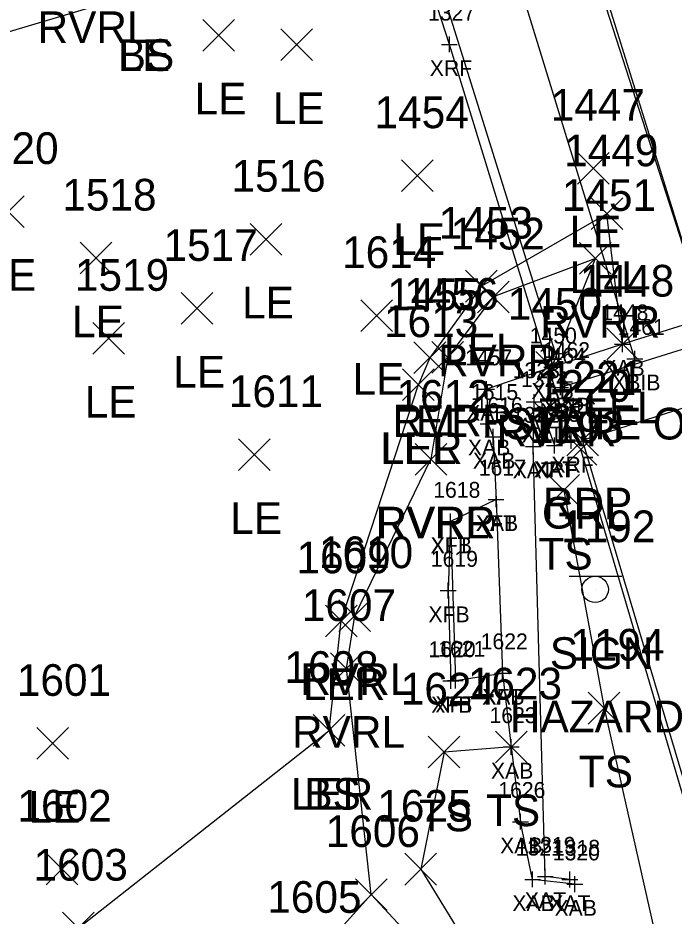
# Model space of a CAD drawing. Extents: x 1620157 to 1620595, y 115111 to 117885.
# Drawn here: x 1620300.9 to 1620342.3, y 115358.6 to 115415.3 of the extents above; entities that cross this region are included whole.
import ezdxf

# ---------------------------------------------------------------- set-up
doc = ezdxf.new("R2010")
doc.units = 0
for name, color, linetype in [('B_A', 7, 'Continuous'), ('B_I', 7, 'Continuous'), ('B_TIC', 7, 'Continuous'), ('BB', 7, 'Continuous'), ('BELB', 7, 'Continuous'), ('BFT', 7, 'Continuous'), ('BR', 7, 'Continuous'), ('BSE', 7, 'Continuous'), ('BSUBM', 7, 'Continuous'), ('C_C', 7, 'Continuous'), ('L_A', 7, 'Continuous'), ('L_I', 7, 'Continuous'), ('L_TIC', 7, 'Continuous'), ('LARO', 7, 'Continuous'), ('LAWE', 7, 'Continuous'), ('LELB', 7, 'Continuous'), ('P_A', 7, 'Continuous'), ('P_I', 7, 'Continuous'), ('P_TIC', 7, 'Continuous'), ('PET', 7, 'Continuous'), ('R_A', 7, 'Continuous'), ('R_I', 7, 'Continuous'), ('R_TIC', 7, 'Continuous'), ('RGR', 7, 'Continuous'), ('S_A', 7, 'Continuous'), ('S_C', 7, 'Continuous'), ('S_I', 7, 'Continuous'), ('SSGN', 7, 'Continuous')]:
    doc.layers.add(name, color=color, linetype=linetype)

msp = doc.modelspace()

# ---------------------------------------------------------------- linework, layer by layer
at = {"layer": 'B_TIC'}
for p, q in [((1620328.105, 115413.59), (1620328.18, 115413.59)), ((1620339.038, 115394.674), (1620339.113, 115394.674)), ((1620339.811, 115393.755), (1620339.886, 115393.755)), ((1620334.567, 115393.214), (1620334.642, 115393.214)), ((1620335.378, 115392.294), (1620335.453, 115392.294)), ((1620330.443, 115391.836), (1620330.519, 115391.836)), ((1620335.116, 115391.945), (1620335.192, 115391.945)), ((1620333.45, 115391.022), (1620333.525, 115391.022)), ((1620333.966, 115390.461), (1620334.041, 115390.461)), ((1620330.556, 115389.649), (1620330.631, 115389.649)), ((1620330.873, 115388.823), (1620330.949, 115388.823)), ((1620335.783, 115388.568), (1620335.858, 115388.568)), ((1620333.4, 115388.211), (1620333.476, 115388.211)), ((1620334.734, 115388.271), (1620334.809, 115388.271)), ((1620334.734, 115388.271), (1620334.809, 115388.271)), ((1620331.048, 115384.876), (1620331.124, 115384.876)), ((1620331.048, 115384.876), (1620331.124, 115384.876)), ((1620328.171, 115383.477), (1620328.247, 115383.477)), ((1620328.171, 115383.477), (1620328.247, 115383.477)), ((1620328.024, 115379.121), (1620328.099, 115379.121)), ((1620331.449, 115373.918), (1620331.525, 115373.918)), ((1620331.449, 115373.918), (1620331.525, 115373.918)), ((1620328.199, 115373.416), (1620328.275, 115373.416)), ((1620328.484, 115373.445), (1620328.559, 115373.445)), ((1620332.008, 115369.254), (1620332.083, 115369.254)), ((1620332.589, 115364.537), (1620332.664, 115364.537)), ((1620332.589, 115364.537), (1620332.664, 115364.537)), ((1620334.16, 115361.076), (1620334.236, 115361.076)), ((1620333.361, 115360.897), (1620333.436, 115360.897)), ((1620335.71, 115360.89), (1620335.785, 115360.89)), ((1620336.021, 115360.595), (1620336.097, 115360.595))]:
    msp.add_line(p, q, dxfattribs=at)
for points in [[(1620328.101, 115413.09), (1620328.101, 115414.09)], [(1620327.601, 115413.59), (1620328.601, 115413.59)], [(1620339.034, 115394.174), (1620339.034, 115395.174)], [(1620338.534, 115394.674), (1620339.534, 115394.674)], [(1620339.807, 115393.255), (1620339.807, 115394.255)], [(1620334.564, 115392.714), (1620334.564, 115393.714)], [(1620339.307, 115393.755), (1620340.307, 115393.755)], [(1620334.064, 115393.214), (1620335.064, 115393.214)], [(1620330.44, 115391.336), (1620330.44, 115392.336)], [(1620334.874, 115392.294), (1620335.874, 115392.294)], [(1620335.113, 115391.445), (1620335.113, 115392.445)], [(1620335.374, 115391.794), (1620335.374, 115392.794)], [(1620329.94, 115391.836), (1620330.94, 115391.836)], [(1620334.613, 115391.945), (1620335.613, 115391.945)], [(1620333.446, 115390.522), (1620333.446, 115391.522)], [(1620332.946, 115391.022), (1620333.946, 115391.022)], [(1620333.962, 115389.961), (1620333.962, 115390.961)], [(1620330.552, 115389.149), (1620330.552, 115390.149)], [(1620333.462, 115390.461), (1620334.462, 115390.461)], [(1620330.052, 115389.649), (1620331.052, 115389.649)], [(1620330.87, 115388.323), (1620330.87, 115389.323)], [(1620335.779, 115388.068), (1620335.779, 115389.068)], [(1620330.37, 115388.823), (1620331.37, 115388.823)], [(1620333.397, 115387.711), (1620333.397, 115388.711)], [(1620334.73, 115387.771), (1620334.73, 115388.771)], [(1620334.73, 115387.771), (1620334.73, 115388.771)], [(1620335.279, 115388.568), (1620336.279, 115388.568)], [(1620332.897, 115388.211), (1620333.897, 115388.211)], [(1620334.23, 115388.271), (1620335.23, 115388.271)], [(1620334.23, 115388.271), (1620335.23, 115388.271)], [(1620330.545, 115384.876), (1620331.545, 115384.876)], [(1620330.545, 115384.876), (1620331.545, 115384.876)], [(1620331.045, 115384.376), (1620331.045, 115385.376)], [(1620331.045, 115384.376), (1620331.045, 115385.376)], [(1620328.168, 115382.977), (1620328.168, 115383.977)], [(1620328.168, 115382.977), (1620328.168, 115383.977)], [(1620327.668, 115383.477), (1620328.668, 115383.477)], [(1620327.668, 115383.477), (1620328.668, 115383.477)], [(1620328.02, 115378.621), (1620328.02, 115379.621)], [(1620327.52, 115379.121), (1620328.52, 115379.121)], [(1620331.446, 115373.418), (1620331.446, 115374.418)], [(1620331.446, 115373.418), (1620331.446, 115374.418)], [(1620328.196, 115372.916), (1620328.196, 115373.916)], [(1620328.48, 115372.945), (1620328.48, 115373.945)], [(1620330.946, 115373.918), (1620331.946, 115373.918)], [(1620330.946, 115373.918), (1620331.946, 115373.918)], [(1620327.696, 115373.416), (1620328.696, 115373.416)], [(1620327.98, 115373.445), (1620328.98, 115373.445)], [(1620332.004, 115368.754), (1620332.004, 115369.754)], [(1620331.504, 115369.254), (1620332.504, 115369.254)], [(1620332.085, 115364.537), (1620333.085, 115364.537)], [(1620332.085, 115364.537), (1620333.085, 115364.537)], [(1620332.585, 115364.037), (1620332.585, 115365.037)], [(1620332.585, 115364.037), (1620332.585, 115365.037)], [(1620333.357, 115360.397), (1620333.357, 115361.397)], [(1620333.657, 115361.076), (1620334.657, 115361.076)], [(1620334.157, 115360.576), (1620334.157, 115361.576)], [(1620335.706, 115360.39), (1620335.706, 115361.39)], [(1620336.018, 115360.095), (1620336.018, 115361.095)], [(1620332.857, 115360.897), (1620333.857, 115360.897)], [(1620335.206, 115360.89), (1620336.206, 115360.89)], [(1620335.518, 115360.595), (1620336.518, 115360.595)]]:
    msp.add_lwpolyline(points, dxfattribs=at)
at = {"layer": 'BB'}
for points in [[(1620344.626, 115395.358), (1620331.032, 115439.016)], [(1620339.807, 115393.755), (1620326.34, 115437.517)], [(1620335.374, 115392.294), (1620321.717, 115436.005)]]:
    msp.add_lwpolyline(points, dxfattribs=at)
at = {"layer": 'BELB'}
msp.add_lwpolyline([(1620336.951, 115419.174), (1620345.538, 115392.547)], dxfattribs=at)
at = {"layer": 'BFT'}
for points in [[(1620331.045, 115384.876), (1620328.168, 115383.477), (1620328.48, 115373.445), (1620331.446, 115373.918)], [(1620328.168, 115383.477), (1620328.02, 115379.121), (1620328.196, 115373.416)]]:
    msp.add_lwpolyline(points, dxfattribs=at)
at = {"layer": 'BR'}
msp.add_lwpolyline([(1620334.73, 115388.271), (1620335.779, 115388.568), (1620328.101, 115413.59), (1620319.786, 115439.283), (1620318.424, 115439.117), (1620318.652, 115437.704)], dxfattribs=at)
at = {"layer": 'BSE'}
msp.add_lwpolyline([(1620355.066, 115398.165), (1620335.113, 115391.945)], dxfattribs=at)
at = {"layer": 'BSUBM'}
for points in [[(1620372.986, 115377.653), (1620373.48, 115377.958), (1620366.01, 115389.074), (1620362.986, 115393.449), (1620359.485, 115398.989), (1620358.358, 115400.738), (1620339.034, 115394.674), (1620334.564, 115393.214), (1620330.44, 115391.836), (1620330.552, 115389.649), (1620330.87, 115388.823), (1620331.045, 115384.876), (1620331.446, 115373.918), (1620332.004, 115369.254), (1620332.585, 115364.537)], [(1620335.706, 115360.89), (1620334.157, 115361.076), (1620333.397, 115388.211), (1620333.446, 115391.022), (1620333.962, 115390.461), (1620334.73, 115388.271)], [(1620336.018, 115360.595), (1620333.357, 115360.897), (1620332.585, 115364.537)]]:
    msp.add_lwpolyline(points, dxfattribs=at)
at = {"layer": 'L_TIC'}
for points in [[(1620312.533, 115413.168), (1620314.533, 115415.168)], [(1620314.533, 115413.168), (1620312.533, 115415.168)], [(1620317.465, 115412.563), (1620319.465, 115414.563)], [(1620319.465, 115412.563), (1620317.465, 115414.563)], [(1620336.19, 115404.771), (1620338.19, 115406.771)], [(1620338.19, 115404.771), (1620336.19, 115406.771)], [(1620325.068, 115404.301), (1620327.068, 115406.301)], [(1620327.068, 115404.301), (1620325.068, 115406.301)], [(1620299.263, 115402.04), (1620301.263, 115404.04)], [(1620301.263, 115402.04), (1620299.263, 115404.04)], [(1620337.044, 115401.898), (1620339.044, 115403.898)], [(1620339.044, 115401.898), (1620337.044, 115403.898)], [(1620315.524, 115400.293), (1620317.524, 115402.293)], [(1620317.524, 115400.293), (1620315.524, 115402.293)], [(1620304.791, 115399.102), (1620306.791, 115401.102)], [(1620306.791, 115399.102), (1620304.791, 115401.102)], [(1620336.323, 115399.079), (1620338.323, 115401.079)], [(1620338.323, 115399.079), (1620336.323, 115401.079)], [(1620329.122, 115397.33), (1620331.122, 115399.33)], [(1620331.122, 115397.33), (1620329.122, 115399.33)], [(1620329.874, 115396.648), (1620331.874, 115398.648)], [(1620331.874, 115396.648), (1620329.874, 115398.648)], [(1620311.177, 115395.925), (1620313.177, 115397.925)], [(1620313.177, 115395.925), (1620311.177, 115397.925)], [(1620322.501, 115395.474), (1620324.501, 115397.474)], [(1620324.501, 115395.474), (1620322.501, 115397.474)], [(1620305.594, 115394.038), (1620307.594, 115396.038)], [(1620307.594, 115394.038), (1620305.594, 115396.038)], [(1620338.034, 115393.674), (1620340.034, 115395.674)], [(1620340.034, 115393.674), (1620338.034, 115395.674)], [(1620325.867, 115392.815), (1620327.867, 115394.815)], [(1620327.867, 115392.815), (1620325.867, 115394.815)], [(1620326.996, 115392.844), (1620328.996, 115394.844)], [(1620328.996, 115392.844), (1620326.996, 115394.844)], [(1620333.564, 115392.214), (1620335.564, 115394.214)], [(1620335.564, 115392.214), (1620333.564, 115394.214)], [(1620325.145, 115391.116), (1620327.145, 115393.116)], [(1620327.145, 115391.116), (1620325.145, 115393.116)], [(1620325.145, 115391.116), (1620327.145, 115393.116)], [(1620327.145, 115391.116), (1620325.145, 115393.116)], [(1620314.785, 115386.696), (1620316.785, 115388.696)], [(1620316.785, 115386.696), (1620314.785, 115388.696)], [(1620325.931, 115386.408), (1620327.931, 115388.408)], [(1620327.931, 115386.408), (1620325.931, 115388.408)], [(1620325.931, 115386.408), (1620327.931, 115388.408)], [(1620327.931, 115386.408), (1620325.931, 115388.408)], [(1620334.319, 115384.442), (1620336.319, 115386.442)], [(1620336.319, 115384.442), (1620334.319, 115386.442)], [(1620320.276, 115376.21), (1620322.276, 115378.21)], [(1620322.276, 115376.21), (1620320.276, 115378.21)], [(1620321.123, 115376.536), (1620323.123, 115378.536)], [(1620323.123, 115376.536), (1620321.123, 115378.536)], [(1620320.602, 115373.201), (1620322.602, 115375.201)], [(1620322.602, 115373.201), (1620320.602, 115375.201)], [(1620336.864, 115370.7), (1620338.864, 115372.7)], [(1620338.864, 115370.7), (1620336.864, 115372.7)], [(1620319.504, 115369.294), (1620321.504, 115371.294)], [(1620321.504, 115369.294), (1620319.504, 115371.294)], [(1620319.504, 115369.294), (1620321.504, 115371.294)], [(1620321.504, 115369.294), (1620319.504, 115371.294)], [(1620302.048, 115368.476), (1620304.048, 115370.476)], [(1620304.048, 115368.476), (1620302.048, 115370.476)], [(1620331.004, 115368.254), (1620333.004, 115370.254)], [(1620333.004, 115368.254), (1620331.004, 115370.254)], [(1620326.77, 115367.93), (1620328.77, 115369.93)], [(1620328.77, 115367.93), (1620326.77, 115369.93)], [(1620302.651, 115360.543), (1620304.651, 115362.543)], [(1620304.651, 115360.543), (1620302.651, 115362.543)], [(1620325.291, 115360.539), (1620327.291, 115362.539)], [(1620327.291, 115360.539), (1620325.291, 115362.539)], [(1620322.167, 115358.94), (1620324.167, 115360.94)], [(1620324.167, 115358.94), (1620322.167, 115360.94)], [(1620322.167, 115358.94), (1620324.167, 115360.94)], [(1620324.167, 115358.94), (1620322.167, 115360.94)], [(1620303.673, 115356.818), (1620305.673, 115358.818)], [(1620305.673, 115356.818), (1620303.673, 115358.818)]]:
    msp.add_lwpolyline(points, dxfattribs=at)
at = {"layer": 'LARO'}
for points in [[(1620339.034, 115394.674), (1620338.044, 115402.898), (1620330.122, 115398.33), (1620326.867, 115393.815), (1620326.145, 115392.116)], [(1620320.504, 115370.294), (1620321.276, 115377.21), (1620326.145, 115392.116)]]:
    msp.add_lwpolyline(points, dxfattribs=at)
at = {"layer": 'LAWE'}
for points in [[(1620334.564, 115393.214), (1620337.323, 115400.079), (1620330.874, 115397.648), (1620327.996, 115393.844), (1620326.931, 115387.408)], [(1620231.187, 115341.28), (1620255.832, 115340.835), (1620271.825, 115342.909), (1620282.718, 115349.37), (1620290.514, 115351.088), (1620308.474, 115349.924), (1620319.423, 115355.785), (1620323.167, 115359.94), (1620321.602, 115374.201), (1620322.123, 115377.536), (1620326.931, 115387.408)]]:
    msp.add_lwpolyline(points, dxfattribs=at)
at = {"layer": 'LELB'}
for points in [[(1620445.933, 115434.696), (1620432.19, 115440.311), (1620415.154, 115443.989), (1620397.761, 115444.055), (1620388.34, 115442.493), (1620368.19, 115442.372), (1620354.516, 115441.049), (1620350.878, 115433.955), (1620346.485, 115432.501), (1620338.973, 115434.365), (1620325.326, 115430.427), (1620316.032, 115427.322), (1620308.723, 115416.914), (1620294.485, 115412.65), (1620281.316, 115408.44), (1620263.956, 115399.244), (1620237.914, 115391.699), (1620225.014, 115391.235), (1620212.858, 115385.97)], [(1620335.319, 115385.442), (1620337.864, 115371.7), (1620343.561, 115346.497), (1620341.166, 115344.372)], [(1620230.717, 115342.258), (1620255.446, 115343.763), (1620266.003, 115344.013), (1620278.661, 115350.372), (1620291.124, 115352.303), (1620304.673, 115357.818), (1620320.504, 115370.294)], [(1620332.004, 115369.254), (1620327.77, 115368.93), (1620326.291, 115361.539), (1620331.798, 115352.573), (1620335.893, 115347.526), (1620330.791, 115343.259), (1620318.913, 115350.016), (1620306.405, 115344.415), (1620294.346, 115343.273), (1620287.578, 115341.357), (1620278.524, 115334.856), (1620255.739, 115323.043)], [(1620323.167, 115359.94), (1620332.761, 115349.618), (1620330.957, 115346.97)]]:
    msp.add_lwpolyline(points, dxfattribs=at)
at = {"layer": 'P_TIC'}
for points in [[(1620335.512, 115387.614), (1620337.512, 115389.614)], [(1620337.512, 115387.614), (1620335.512, 115389.614)]]:
    msp.add_lwpolyline(points, dxfattribs=at)
at = {"layer": 'PET'}
msp.add_lwpolyline([(1620562.045, 115139.537), (1620535.961, 115156.898), (1620508.491, 115175.945), (1620479.205, 115196.111), (1620451.098, 115216.616), (1620428.041, 115234.702), (1620407.201, 115256.439), (1620380.209, 115287.874), (1620366.182, 115309.187), (1620356.593, 115324.555), (1620350.492, 115341.932), (1620344.694, 115361.164), (1620336.512, 115388.614), (1620345.687, 115391.553), (1620355.301, 115394.861)], dxfattribs=at)
at = {"layer": 'R_TIC'}
for points in [[(1620335.401, 115387.033), (1620337.401, 115389.033)], [(1620337.401, 115387.033), (1620335.401, 115389.033)]]:
    msp.add_lwpolyline(points, dxfattribs=at)
at = {"layer": 'RGR'}
msp.add_lwpolyline([(1620346.982, 115317.888), (1620350.804, 115321.196), (1620352.683, 115325.401), (1620352.529, 115329.549), (1620349.57, 115341.57), (1620344.313, 115361.225), (1620336.401, 115388.033)], dxfattribs=at)
at = {"layer": 'SSGN'}
for p, q in [((1620335.655, 115380.028), (1620338.989, 115380.028)), ((1620337.302, 115379.195), (1620337.302, 115379.195))]:
    msp.add_line(p, q, dxfattribs=at)
msp.add_circle((1620337.302, 115379.195), 0.833, dxfattribs=at)

# ---------------------------------------------------------------- texts
at = {"layer": 'B_A'}
for s, p in [('XRF', (1620326.861, 115411.59)), ('XAB', (1620337.755, 115392.674)), ('XBIB', (1620338.378, 115391.755)), ('XAB', (1620333.284, 115391.214)), ('XBIB', (1620333.945, 115390.294)), ('XAB', (1620329.16, 115389.836)), ('XBS', (1620333.853, 115389.945)), ('XAT', (1620332.151, 115389.022)), ('XAT', (1620332.667, 115388.461)), ('XAB', (1620329.273, 115387.649)), ('XAB', (1620329.59, 115386.823)), ('XAT', (1620332.101, 115386.211)), ('XAT', (1620333.435, 115386.271)), ('XRF', (1620333.49, 115386.271)), ('XRF', (1620334.539, 115386.568)), ('XAB', (1620329.765, 115382.876)), ('XFT', (1620329.789, 115382.876)), ('XFT', (1620326.912, 115381.477)), ('XFB', (1620326.928, 115381.477)), ('XFB', (1620326.78, 115377.121)), ('XFB', (1620326.956, 115371.416)), ('XFT', (1620327.224, 115371.445)), ('XAB', (1620330.166, 115371.918)), ('XFT', (1620330.19, 115371.918)), ('XAB', (1620330.725, 115367.254)), ('XAB', (1620331.306, 115362.537)), ('XAB', (1620331.306, 115362.537)), ('XAT', (1620332.862, 115359.076)), ('XAB', (1620332.078, 115358.897)), ('XAT', (1620334.411, 115358.89)), ('XAB', (1620334.738, 115358.595))]:
    msp.add_text(s, height=1, dxfattribs=at).set_placement(p)
at = {"layer": 'B_I'}
for s, p in [('1327', (1620326.755, 115415.09)), ('1448', (1620337.688, 115396.174)), ('1461', (1620338.721, 115395.255)), ('1450', (1620333.174, 115394.714)), ('1462', (1620334.004, 115393.794)), ('1457', (1620329.093, 115393.336)), ('1464', (1620333.743, 115393.445)), ('1323', (1620332.1, 115392.522)), ('1324', (1620332.616, 115391.961)), ('1615', (1620329.466, 115391.149)), ('1616', (1620329.756, 115390.323)), ('1322', (1620332.05, 115389.711)), ('1325', (1620333.384, 115389.771)), ('1325', (1620333.384, 115389.771)), ('1326', (1620334.406, 115390.068)), ('1617', (1620329.958, 115386.376)), ('1617', (1620329.958, 115386.376)), ('1618', (1620327.081, 115384.977)), ('1618', (1620327.081, 115384.977)), ('1619', (1620326.93, 115380.621)), ('1622', (1620330.076, 115375.418)), ('1622', (1620330.076, 115375.418)), ('1620', (1620326.783, 115374.916)), ('1621', (1620327.394, 115374.945)), ('1623', (1620330.634, 115370.754)), ('1626', (1620331.188, 115366.037)), ('1626', (1620331.188, 115366.037)), ('1321', (1620332.295, 115362.397)), ('1319', (1620333.09, 115362.576)), ('1318', (1620334.643, 115362.39)), ('1320', (1620334.628, 115362.095))]:
    msp.add_text(s, height=1, dxfattribs=at).set_placement(p)
at = {"layer": 'C_C'}
msp.add_text('STATE OF VERMONT SURVEY MARK', height=2, dxfattribs=at).set_placement((1620331.593, 115388.655))
at = {"layer": 'L_A'}
for s, p in [('RVRL', (1620302.101, 115413.672)), ('BS', (1620307.164, 115411.914)), ('LE', (1620307.212, 115411.914)), ('LE', (1620312.021, 115409.168)), ('LE', (1620316.953, 115408.563)), ('LE', (1620335.678, 115400.771)), ('LE', (1620324.557, 115400.301)), ('LE', (1620298.752, 115398.04)), ('LEL', (1620335.681, 115397.898)), ('LE', (1620315.012, 115396.293)), ('LE', (1620304.279, 115395.102)), ('RVRR', (1620333.835, 115395.079)), ('LEL', (1620327.76, 115393.33)), ('RVRR', (1620327.386, 115392.648)), ('LE', (1620310.665, 115391.925)), ('LE', (1620321.989, 115391.474)), ('LE', (1620305.082, 115390.038)), ('LEL', (1620336.672, 115389.674)), ('LEL', (1620324.505, 115388.815)), ('RVRR', (1620324.508, 115388.844)), ('RVRR', (1620331.075, 115388.214)), ('LER', (1620323.728, 115387.116)), ('LEL', (1620323.783, 115387.116)), ('LE', (1620314.273, 115382.696)), ('RVRR', (1620323.443, 115382.408)), ('RVRL', (1620323.498, 115382.408)), ('TS', (1620333.728, 115380.442)), ('RVRL', (1620318.69, 115372.536)), ('LER', (1620318.858, 115372.21)), ('RVRL', (1620318.169, 115369.201)), ('TS', (1620336.273, 115366.7)), ('BS', (1620318.945, 115365.294)), ('LER', (1620318.087, 115365.294)), ('LE', (1620301.536, 115364.476)), ('TS', (1620330.414, 115364.254)), ('TS', (1620326.179, 115363.93))]:
    msp.add_text(s, height=2, dxfattribs=at).set_placement(p)
at = {"layer": 'L_I'}
for s, p in [('1447', (1620334.497, 115408.771)), ('1454', (1620323.376, 115408.301)), ('1520', (1620297.484, 115406.04)), ('1449', (1620335.343, 115405.898)), ('1516', (1620314.343, 115404.293)), ('1518', (1620303.665, 115403.102)), ('1451', (1620335.197, 115403.079)), ('1453', (1620327.429, 115401.33)), ('1452', (1620328.182, 115400.648)), ('1517', (1620310.051, 115399.925)), ('1614', (1620321.328, 115399.474)), ('1519', (1620304.461, 115398.038)), ('1448', (1620336.341, 115397.674)), ('1455', (1620324.175, 115396.815)), ('1456', (1620325.248, 115396.844)), ('1450', (1620331.784, 115396.214)), ('1613', (1620323.972, 115395.116)), ('1613', (1620323.972, 115395.116)), ('1611', (1620314.179, 115390.696)), ('1612', (1620324.758, 115390.408)), ('1612', (1620324.758, 115390.408)), ('1193', (1620333.193, 115388.442)), ('1609', (1620318.449, 115380.21)), ('1610', (1620319.863, 115380.536)), ('1607', (1620318.783, 115377.201)), ('1194', (1620335.738, 115374.7)), ('1608', (1620317.685, 115373.294)), ('1608', (1620317.685, 115373.294)), ('1601', (1620300.796, 115372.476)), ('1623', (1620329.264, 115372.254)), ('1624', (1620325.03, 115371.93)), ('1602', (1620300.832, 115364.543)), ('1625', (1620323.551, 115364.539)), ('1606', (1620320.293, 115362.94)), ('1606', (1620320.293, 115362.94)), ('1603', (1620301.854, 115360.818)), ('1605', (1620316.605, 115358.785)), ('1605', (1620316.605, 115358.785))]:
    msp.add_text(s, height=2, dxfattribs=at).set_placement(p)
at = {"layer": 'P_A'}
msp.add_text('RDP', height=2, dxfattribs=at).set_placement((1620334, 115383.614))
at = {"layer": 'P_I'}
msp.add_text('1221', height=2, dxfattribs=at).set_placement((1620334.386, 115391.614))
at = {"layer": 'R_A'}
msp.add_text('GRL', height=2, dxfattribs=at).set_placement((1620333.944, 115383.033))
at = {"layer": 'R_I'}
msp.add_text('1220', height=2, dxfattribs=at).set_placement((1620333.622, 115391.033))
at = {"layer": 'S_A'}
msp.add_text('SIGN', height=2, dxfattribs=at).set_placement((1620334.44, 115374.175))
at = {"layer": 'S_C'}
msp.add_text('HAZARD', height=2, dxfattribs=at).set_placement((1620331.921, 115370.175))
at = {"layer": 'S_I'}
msp.add_text('1192', height=2, dxfattribs=at).set_placement((1620335.157, 115382.175))

doc.saveas('drawing.dxf')
